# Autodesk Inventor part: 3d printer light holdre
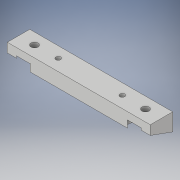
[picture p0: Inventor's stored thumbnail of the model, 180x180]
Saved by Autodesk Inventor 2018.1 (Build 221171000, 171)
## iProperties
Created: 2018-03
Part Number: 3d printer light holdre
Material: Generic
Document SubType Name: Modeling
Designer: jdice
Density: 1 g/cm^3
Appearance: Default
Author: jdice
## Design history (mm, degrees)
sketch "Sketch1"
  geometry: L1 (0, 0)-(0, -9.42); L2 (0, -9.42)-(-9.429, -9.42); L3 (-9.429, -9.42)-(-6, 0); L4 (-6, 0)-(0, 0)
  constraints: 8 end point, 1 parallel, 1 perpendicular, 1 vertical
  dimensions: "d0" = 9.42 distance between parallel lines of L2 L4; "d1" = 110 deg angle of L4 L3; "d2" = 6 distance from line of L3.end L1
extrude "Extrusion1" new body sketch "Sketch1" distance "d3" = 60; taper "d4" = 0 deg
sketch "Sketch2"
  geometry: L1 (0, 0)-(0, 9.42) reference; L2 (0, 0)-(60, 0) reference; L3 (60, 9.42)-(60, 0) reference; L4 (0, 9.42)-(60, 9.42) reference; 3 further points
  constraints: 1 horizontal alignment
  dimensions: "d5" = 4.71 distance from line of point (53.29, 4.71) L4; "d6" = 6.71 distance from line of point (53.29, 4.71) L3; "d7" = 6.71 distance from line of L1 point (6.71, 4.71)
hole "Hole1" sketch "Sketch2" at (6.71, 4.71), (53.29, 4.71) diameter "d8" = 3; stored, may be unused: countersink angle "d12" = 90 deg, drill point angle "d14" = 118 deg; dims "d9" = 6, "d10" = 4, "d11" = 2, "d13" = 8
workplane "Work Plane1"
sketch "Sketch3"
  geometry: C1 r 1.5 at (53.29, 4.71) reference; C2 r 5.5 at (53.29, 4.71); C3 r 1.5 at (6.71, 4.71) reference; C4 r 1.5 at (6.71, 4.71) reference; C5 r 5.5 at (6.71, 4.71); 1 further point
  constraints: 2 centre point, 2 coincident
  dimensions: "d16" = 11 diameter of C2; "d17" = 11 diameter of C5
extrude "Extrusion2" cut sketch "Sketch3" distance "d18" = 7; taper "d19" = 0 deg
sketch "Sketch6"
  geometry: L1 (-9.55, -10.025)-(-9.55, 0) reference; L2 (0, -10.025)-(40.9, -10.025) reference; L3 (0, 0)-(40.9, 0) reference; 3 further points
  constraints: 1 horizontal alignment
  dimensions: "d20" = 26.9 distance of point (33.9, -2.5) point (7, -2.5); "d21" = 16.55 distance from line of L1 point (7, -2.5); "d23" = 2.5 distance from line of point (7, -2.5) L3
hole "Hole2" sketch "Sketch6" at (7, -2.5), (33.9, -2.5) diameter "d24" = 1.97; stored, may be unused: countersink angle "d28" = 90 deg, drill point angle "d30" = 0 deg; dims "d25" = 6, "d26" = 4, "d27" = 2, "d29" = 11
sketch "Sketch7"
  geometry: L1 (-9.55, -10.025)-(-5.68, -10.025) reference; L2 (0, 0)-(40.9, 0) reference; L3 (-9.55, -10.025)-(-0.05, -10.025); L4 (-0.05, -10.025)-(-0.05, 4.975); L5 (-9.55, 4.975)-(-9.55, -10.025); L6 (50.45, -10.025)-(50.45, -6.8) reference; L7 (50.45, -10.025)-(40.95, -10.025); L8 (40.95, -10.025)-(40.95, 4.975); L9 (50.45, 4.975)-(50.45, -10.025); L10 (-0.05, -10.025)-(-0.05, 4.975); L11 (-0.05, 4.975)-(-9.55, 4.975); L12 (-9.55, 4.975)-(-9.55, 0); L13 (50.45, 0)-(50.45, 4.975); L14 (50.45, 4.975)-(40.95, 4.975); L15 (40.95, 4.975)-(40.95, 0); 1 further point
  constraints: 24 end point, 4 parallel, 2 equal length, 2 horizontal, 2 perpendicular, 2 point on line
  dimensions: "d31" = 41 distance between parallel lines of L4 L8; "d32" = 15 distance between parallel lines of L7 L14
extrude "Extrusion3" cut sketch "Sketch7" distance "d33" = 2; taper "d34" = 0 deg
body "Solid1"
node "Projected Loop1"
